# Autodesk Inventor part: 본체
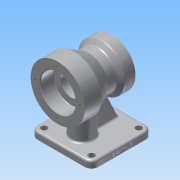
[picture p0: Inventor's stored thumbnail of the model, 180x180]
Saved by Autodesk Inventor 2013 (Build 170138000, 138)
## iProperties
Created: 2019-01
Part Number: 본체
Material: 알루미늄 6061
Document SubType Name: Modeling
Designer: Administrator
Density: 2.71 g/cm^3
Mass: 890.461 g
Surface Area: 592.046 cm^2
Volume: 328.583 cm^3
Author: Administrator
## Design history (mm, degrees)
sketch "스케치1"
  geometry: L1 (0, 26)-(0, 40); L2 (0, 40)-(25, 40); L3 (25, 40)-(45.785, 28); L4 (45.785, 28)-(59.126, 28); L5 (59.126, 28)-(65, 35); L6 (65, 35)-(80, 35); L7 (80, 35)-(80, 20); L8 (80, 20)-(63, 20); L9 (63, 20)-(63, 16); L10 (63, 16)-(20, 16); L11 (20, 16)-(20, 26); L12 (20, 26)-(0, 26); L13 (0, 0)-(80, 0)
  constraints: 26 end point, 8 parallel, 2 perpendicular, 2 point on line, 1 vertical
  dimensions: "d0" = 25 distance of L1.end L2.end; "d2" = 15 distance of L5.end L6.end; "d4" = 52 diameter of L12 L13; "d5" = 32 diameter of L10 L13; "d6" = 40 diameter of L8 L13; "d7" = 56 diameter of L4 L13; "d8" = 70 diameter of L6 L13; "d9" = 80 diameter of L2 L13; "d10" = 80 distance between parallel lines of L7 L1; "d11" = 20 distance of L11.end L1.start; "d12" = 17 distance of L7.end L8.end; "d13" = 30 deg angle of L3 L4; "d14" = 50 deg angle of L4 L5
revolve "회전1" sketch "스케치1" stored, may be unused: angle "d15" = 90 deg
node "작업 평면1"
sketch "스케치2"
  geometry: L1 (-5, 45)-(-95, 45); L2 (-95, 45)-(-95, -45); L3 (-95, -45)-(-5, -45); L4 (-5, -45)-(-5, 45); L5 (-5, 45)-(-95, -45); L6 (-95, 45)-(-5, -45); L7 (0, 40)-(0, -40) reference; 4 further points
  constraints: 12 end point, 4 midpoint, 2 parallel, 1 horizontal, 1 horizontal alignment, 1 perpendicular
  dimensions: "d17" = 90 distance of L3.end L2.end; "d18" = 90 distance of L2.end L1.end; "d19" = 5 distance from line of L1.start L7
extrude "돌출1" join sketch "스케치2" distance "d20" = 10; taper "d21" = 0 deg
sketch "스케치3"
  geometry: L1 (5, 45)-(5, -45) reference; C1 r 16 at (35, -1); 1 further point
  constraints: 1 centre point
  dimensions: "d22" = 16 radius of C1; "d23" = 30 distance from line of L1 C1.centre; "d24" = 46 vertical distance of L1.start C1.centre
extrude "돌출2" join sketch "스케치3" stored distance "d25" = 10; taper "d26" = 0 deg
sketch "스케치4"
  geometry: L1 (51, -70)-(51, -27.982) reference; L2 (95, -70)-(5, -70) reference; L3 (50.969, -28)-(59.126, -28) reference; L4 (59.126, -28)-(65, -35) reference; L5 (68.679, -35)-(85, -70); L6 (95, -80)-(95, -70) reference; L7 (65, -35)-(80, -35) reference; 1 further point
  constraints: 2 end point, 2 point on line
  dimensions: "d27" = 25 deg angle of L5 L6; "d28" = 10 distance of L2.start L5.end
feature "리브1" sketch "스케치4" dims "d29" = 1, "d30" = 10, "d31" = 0, "d32" = 0, "d33" = 1, "d34" = 1
sketch "스케치5"
  geometry: C1 r 16 at (0, 0) reference; 2 further points
  constraints: 1 vertical alignment
  dimensions: "d35" = 33 distance of point (0, 0) point (0, 33)
hole "구멍1" sketch "스케치5" at (0, 33) diameter "d36" = 3.242; stored, may be unused: countersink angle "d40" = 90 deg, drill point angle "d42" = 118 deg; dims "d37" = 9, "d38" = 4, "d39" = 2, "d41" = 11
sketch "스케치6"
  geometry: C1 r 35 at (0, 0) reference; 2 further points
  constraints: 1 vertical alignment
  dimensions: "d46" = 27.5 distance of point (0, 27.5) point (0, 0)
hole "구멍2" sketch "스케치6" at (0, 27.5) diameter "d47" = 3.242; stored, may be unused: countersink angle "d51" = 90 deg, drill point angle "d53" = 118 deg; dims "d48" = 9, "d49" = 4, "d50" = 2, "d52" = 11
fillet "모깎기1" dims "d57" = 10
sketch "스케치7"
  geometry: L1 (95, -35)-(95, 35) reference; L2 (15, -45)-(85, -45) reference; L3 (5, 35)-(5, -35) reference; L4 (85, 45)-(15, 45) reference; A1 r 10 centre (85, 35) between (95, 35) and (85, 45) reference; A2 r 10 centre (85, -35) between (85, -45) and (95, -35) reference; A3 r 10 centre (15, -35) between (5, -35) and (15, -45) reference; A4 r 10 centre (15, 35) between (15, 45) and (5, 35) reference; 5 further points
  constraints: 4 coincident
hole "구멍3" sketch "스케치7" at (15, 35), (85, 35), (85, -35), (15, -35) diameter "d58" = 9; stored, may be unused: countersink angle "d62" = 90 deg, drill point angle "d64" = 0 deg; dims "d59" = 9, "d60" = 4, "d61" = 2, "d63" = 11
node "작업 평면2"
sketch "스케치8"
  geometry: L1 (5, -70)-(5, -80) reference; 2 further points
  constraints: 1 other
  dimensions: "d66" = 46 distance from line of L1 point (51, -76); "d67" = 4 vertical distance of L1.end point (51, -76)
feature "엠보싱1" sketch "스케치8" dims "d0" = 25, "d2" = 15, "d4" = 52, "d5" = 32, "d6" = 40, "d7" = 56, "d8" = 70, "d9" = 80, "d10" = 80, "d11" = 20, "d12" = 17, "d13" = 30 deg, "d14" = 50 deg, "d17" = 90, "d68" = 0.5, "d69" = 0
fillet "모깎기2" dims "d70" = 3
fillet "모깎기3" dims "d71" = 3
fillet "모깎기4" dims "d72" = 1
fillet "모깎기5" dims "d73" = 0.6
chamfer "모따기1" distance "d74" = 1; stored, may be unused: second distance "d75" = 2, angle "d76" = 45 deg
node "솔리드1"
pattern_circular "원형 패턴1" dims angle "d44" = 360 deg
pattern_circular "원형 패턴2" dims angle "d55" = 360 deg
node "투영된 루프1"
other parameters: "d65" = 89
